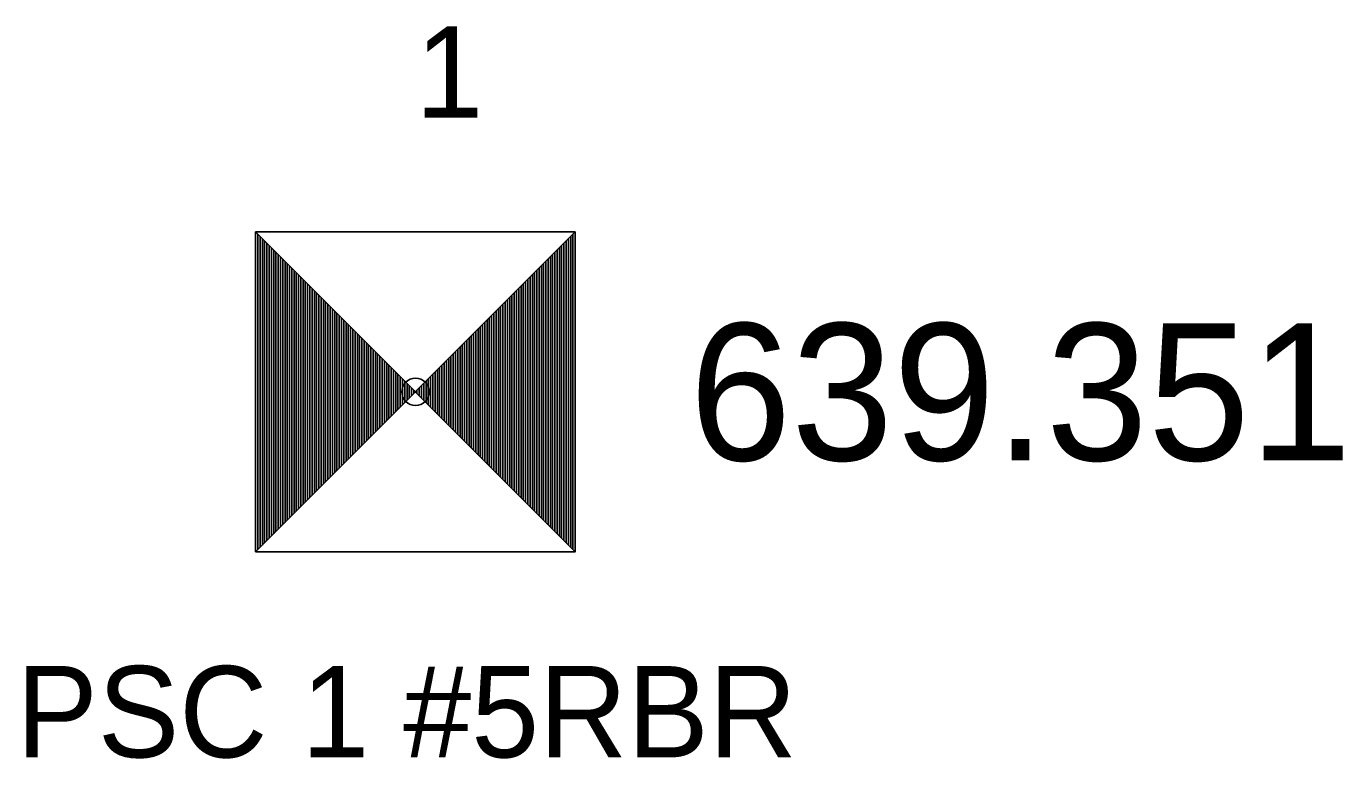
# Model space of a CAD drawing. Extents: x 1694813 to 1696862, y 1086485 to 1091027.
# Drawn here: x 1695712.34 to 1695726.75, y 1086950.61 to 1086958.63 of the extents above; entities that cross this region are included whole.
import ezdxf

# ---------------------------------------------------------------- set-up
doc = ezdxf.new("R2010")
doc.units = 0
for name, color, linetype in [('RD_HC_Survey', 7, 'Continuous'), ('RD_HC_Survey_ELEV', 7, 'Continuous'), ('RD_HC_txCode', 7, 'Continuous'), ('RD_SMD_Locator', 7, 'Continuous')]:
    doc.layers.add(name, color=color, linetype=linetype)

msp = doc.modelspace()

# ---------------------------------------------------------------- linework, layer by layer
at = {"layer": 'RD_HC_Survey'}
for p, q in [((1695714.852, 1086956.375), (1695718.352, 1086952.875)), ((1695718.352, 1086956.375), (1695714.852, 1086952.875)), ((1695714.877, 1086956.35), (1695714.877, 1086952.9)), ((1695718.327, 1086956.35), (1695718.327, 1086952.9)), ((1695714.901, 1086956.326), (1695714.901, 1086952.925)), ((1695714.926, 1086956.301), (1695714.926, 1086952.949)), ((1695714.951, 1086956.276), (1695714.951, 1086952.974)), ((1695714.976, 1086956.251), (1695714.976, 1086952.999)), ((1695715, 1086956.227), (1695715, 1086953.024)), ((1695715.025, 1086956.202), (1695715.025, 1086953.048)), ((1695718.179, 1086956.202), (1695718.179, 1086953.048)), ((1695718.203, 1086956.227), (1695718.203, 1086953.024)), ((1695718.228, 1086956.251), (1695718.228, 1086952.999)), ((1695718.253, 1086956.276), (1695718.253, 1086952.974)), ((1695718.278, 1086956.301), (1695718.278, 1086952.949)), ((1695718.302, 1086956.326), (1695718.302, 1086952.925)), ((1695715.05, 1086956.177), (1695715.05, 1086953.073)), ((1695715.075, 1086956.152), (1695715.075, 1086953.098)), ((1695715.099, 1086956.128), (1695715.099, 1086953.123)), ((1695715.124, 1086956.103), (1695715.124, 1086953.147)), ((1695715.149, 1086956.078), (1695715.149, 1086953.172)), ((1695715.174, 1086956.053), (1695715.174, 1086953.197)), ((1695718.03, 1086956.053), (1695718.03, 1086953.197)), ((1695718.055, 1086956.078), (1695718.055, 1086953.172)), ((1695718.08, 1086956.103), (1695718.08, 1086953.147)), ((1695718.104, 1086956.128), (1695718.104, 1086953.123)), ((1695718.129, 1086956.152), (1695718.129, 1086953.098)), ((1695718.154, 1086956.177), (1695718.154, 1086953.073)), ((1695715.198, 1086956.029), (1695715.198, 1086953.222)), ((1695715.223, 1086956.004), (1695715.223, 1086953.246)), ((1695715.248, 1086955.979), (1695715.248, 1086953.271)), ((1695715.273, 1086955.954), (1695715.273, 1086953.296)), ((1695715.297, 1086955.93), (1695715.297, 1086953.321)), ((1695717.906, 1086955.93), (1695717.906, 1086953.321)), ((1695717.931, 1086955.954), (1695717.931, 1086953.296)), ((1695717.956, 1086955.979), (1695717.956, 1086953.271)), ((1695717.981, 1086956.004), (1695717.981, 1086953.246)), ((1695718.005, 1086956.029), (1695718.005, 1086953.222)), ((1695715.322, 1086955.905), (1695715.322, 1086953.345)), ((1695715.347, 1086955.88), (1695715.347, 1086953.37)), ((1695715.372, 1086955.855), (1695715.372, 1086953.395)), ((1695715.396, 1086955.831), (1695715.396, 1086953.42)), ((1695715.421, 1086955.806), (1695715.421, 1086953.444)), ((1695715.446, 1086955.781), (1695715.446, 1086953.469)), ((1695717.758, 1086955.781), (1695717.758, 1086953.469)), ((1695717.783, 1086955.806), (1695717.783, 1086953.444)), ((1695717.807, 1086955.831), (1695717.807, 1086953.42)), ((1695717.832, 1086955.855), (1695717.832, 1086953.395)), ((1695717.857, 1086955.88), (1695717.857, 1086953.37)), ((1695717.882, 1086955.905), (1695717.882, 1086953.345)), ((1695715.471, 1086955.756), (1695715.471, 1086953.494)), ((1695715.495, 1086955.732), (1695715.495, 1086953.519)), ((1695715.52, 1086955.707), (1695715.52, 1086953.543)), ((1695715.545, 1086955.682), (1695715.545, 1086953.568)), ((1695715.57, 1086955.657), (1695715.57, 1086953.593)), ((1695715.594, 1086955.633), (1695715.594, 1086953.618)), ((1695717.609, 1086955.633), (1695717.609, 1086953.618)), ((1695717.634, 1086955.657), (1695717.634, 1086953.593)), ((1695717.659, 1086955.682), (1695717.659, 1086953.568)), ((1695717.684, 1086955.707), (1695717.684, 1086953.543)), ((1695717.708, 1086955.732), (1695717.708, 1086953.519)), ((1695717.733, 1086955.756), (1695717.733, 1086953.494)), ((1695715.619, 1086955.608), (1695715.619, 1086953.642)), ((1695715.644, 1086955.583), (1695715.644, 1086953.667)), ((1695715.669, 1086955.558), (1695715.669, 1086953.692)), ((1695715.693, 1086955.534), (1695715.693, 1086953.717)), ((1695715.718, 1086955.509), (1695715.718, 1086953.741)), ((1695715.743, 1086955.484), (1695715.743, 1086953.766)), ((1695717.461, 1086955.484), (1695717.461, 1086953.766)), ((1695717.486, 1086955.509), (1695717.486, 1086953.741)), ((1695717.51, 1086955.534), (1695717.51, 1086953.717)), ((1695717.535, 1086955.558), (1695717.535, 1086953.692)), ((1695717.56, 1086955.583), (1695717.56, 1086953.667)), ((1695717.585, 1086955.608), (1695717.585, 1086953.642)), ((1695715.768, 1086955.459), (1695715.768, 1086953.791)), ((1695715.792, 1086955.435), (1695715.792, 1086953.816)), ((1695715.817, 1086955.41), (1695715.817, 1086953.84)), ((1695715.842, 1086955.385), (1695715.842, 1086953.865)), ((1695715.867, 1086955.36), (1695715.867, 1086953.89)), ((1695715.891, 1086955.336), (1695715.891, 1086953.915)), ((1695717.312, 1086955.336), (1695717.312, 1086953.915)), ((1695717.337, 1086955.36), (1695717.337, 1086953.89)), ((1695717.362, 1086955.385), (1695717.362, 1086953.865)), ((1695717.387, 1086955.41), (1695717.387, 1086953.84)), ((1695717.411, 1086955.435), (1695717.411, 1086953.816)), ((1695717.436, 1086955.459), (1695717.436, 1086953.791)), ((1695715.916, 1086955.311), (1695715.916, 1086953.939)), ((1695715.941, 1086955.286), (1695715.941, 1086953.964)), ((1695715.966, 1086955.261), (1695715.966, 1086953.989)), ((1695715.99, 1086955.237), (1695715.99, 1086954.014)), ((1695716.015, 1086955.212), (1695716.015, 1086954.038)), ((1695716.04, 1086955.187), (1695716.04, 1086954.063)), ((1695717.164, 1086955.187), (1695717.164, 1086954.063)), ((1695717.189, 1086955.212), (1695717.189, 1086954.038)), ((1695717.213, 1086955.237), (1695717.213, 1086954.014)), ((1695717.238, 1086955.261), (1695717.238, 1086953.989)), ((1695717.263, 1086955.286), (1695717.263, 1086953.964)), ((1695717.288, 1086955.311), (1695717.288, 1086953.939)), ((1695716.065, 1086955.162), (1695716.065, 1086954.088)), ((1695716.089, 1086955.138), (1695716.089, 1086954.113)), ((1695716.114, 1086955.113), (1695716.114, 1086954.137)), ((1695716.139, 1086955.088), (1695716.139, 1086954.162)), ((1695716.164, 1086955.063), (1695716.164, 1086954.187)), ((1695717.04, 1086955.063), (1695717.04, 1086954.187)), ((1695717.065, 1086955.088), (1695717.065, 1086954.162)), ((1695717.09, 1086955.113), (1695717.09, 1086954.137)), ((1695717.114, 1086955.138), (1695717.114, 1086954.113)), ((1695717.139, 1086955.162), (1695717.139, 1086954.088)), ((1695716.188, 1086955.039), (1695716.188, 1086954.212)), ((1695716.213, 1086955.014), (1695716.213, 1086954.236)), ((1695716.238, 1086954.989), (1695716.238, 1086954.261)), ((1695716.263, 1086954.964), (1695716.263, 1086954.286)), ((1695716.287, 1086954.94), (1695716.287, 1086954.311)), ((1695716.312, 1086954.915), (1695716.312, 1086954.335)), ((1695716.892, 1086954.915), (1695716.892, 1086954.335)), ((1695716.916, 1086954.94), (1695716.916, 1086954.311)), ((1695716.941, 1086954.964), (1695716.941, 1086954.286)), ((1695716.966, 1086954.989), (1695716.966, 1086954.261)), ((1695716.991, 1086955.014), (1695716.991, 1086954.236)), ((1695717.015, 1086955.039), (1695717.015, 1086954.212)), ((1695716.337, 1086954.89), (1695716.337, 1086954.36)), ((1695716.362, 1086954.865), (1695716.362, 1086954.385)), ((1695716.386, 1086954.841), (1695716.386, 1086954.41)), ((1695716.411, 1086954.816), (1695716.411, 1086954.434)), ((1695716.436, 1086954.791), (1695716.436, 1086954.459)), ((1695716.461, 1086954.766), (1695716.461, 1086954.484)), ((1695716.743, 1086954.766), (1695716.743, 1086954.484)), ((1695716.768, 1086954.791), (1695716.768, 1086954.459)), ((1695716.793, 1086954.816), (1695716.793, 1086954.434)), ((1695716.817, 1086954.841), (1695716.817, 1086954.41)), ((1695716.842, 1086954.865), (1695716.842, 1086954.385)), ((1695716.867, 1086954.89), (1695716.867, 1086954.36)), ((1695716.485, 1086954.742), (1695716.485, 1086954.509)), ((1695716.51, 1086954.717), (1695716.51, 1086954.533)), ((1695716.535, 1086954.692), (1695716.535, 1086954.558)), ((1695716.56, 1086954.667), (1695716.56, 1086954.583)), ((1695716.584, 1086954.643), (1695716.584, 1086954.608)), ((1695716.619, 1086954.643), (1695716.619, 1086954.608)), ((1695716.644, 1086954.667), (1695716.644, 1086954.583)), ((1695716.669, 1086954.692), (1695716.669, 1086954.558)), ((1695716.694, 1086954.717), (1695716.694, 1086954.533)), ((1695716.718, 1086954.742), (1695716.718, 1086954.509))]:
    msp.add_line(p, q, dxfattribs=at)
msp.add_lwpolyline([(1695718.352, 1086956.375), (1695714.852, 1086956.375), (1695714.852, 1086952.875), (1695718.352, 1086952.875)], close=True, dxfattribs=at)
at = {"layer": 'RD_SMD_Locator'}
msp.add_circle((1695716.602, 1086954.625), 0.15, dxfattribs=at)

# ---------------------------------------------------------------- texts
at = {"layer": 'RD_HC_Survey_ELEV'}
msp.add_text('639.351', height=1.5, dxfattribs=at).set_placement((1695719.602, 1086953.875))
at = {"layer": 'RD_HC_txCode'}
for s, p in [('1', (1695716.602, 1086957.625)), ('PSC 1 #5RBR', (1695712.232, 1086950.625))]:
    msp.add_text(s, height=1, dxfattribs=at).set_placement(p)

doc.saveas('drawing.dxf')
